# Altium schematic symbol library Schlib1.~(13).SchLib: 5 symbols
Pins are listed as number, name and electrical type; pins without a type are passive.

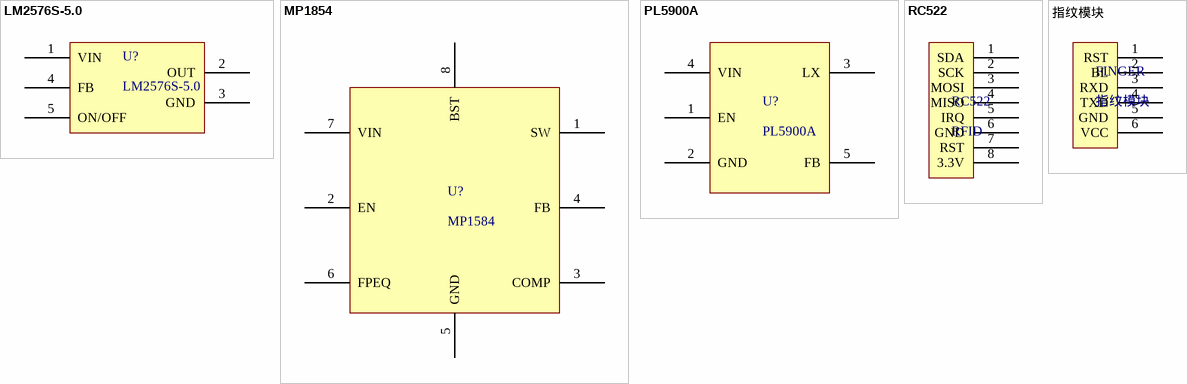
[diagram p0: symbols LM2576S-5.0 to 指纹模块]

## LM2576S-5.0
designator U?
footprint TO263-5A (263，5脚晶体管)
pins: 1 VIN, 2 OUT, 3 GND, 4 FB, 5 ON/OFF

## MP1854
designator U?, comment MP1584
footprint SOP8_L (5*6*1.8mm（长宽高）)
pins: 1 SW, 2 EN, 3 COMP, 4 FB, 5 GND, 6 FPEQ, 7 VIN, 8 BST

## PL5900A
designator U?
footprint SOT23-5L (3x1.6x1.1mm(长宽高))
pins: 1 EN, 2 GND, 3 LX, 4 VIN, 5 FB

## RC522
designator RC522, comment RFID
footprint HDR2.54-LI-8P (排针，8脚)
pins: 1 SDA, 2 SCK, 3 MOSI, 4 MISO, 5 IRQ, 6 GND, 7 RST, 8 3.3V

## 指纹模块
designator FINGER
footprint HDR2.54-LI-6P (排针，6脚)
pins: 1 RST, 2 BL, 3 RXD, 4 TXD, 5 GND, 6 VCC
